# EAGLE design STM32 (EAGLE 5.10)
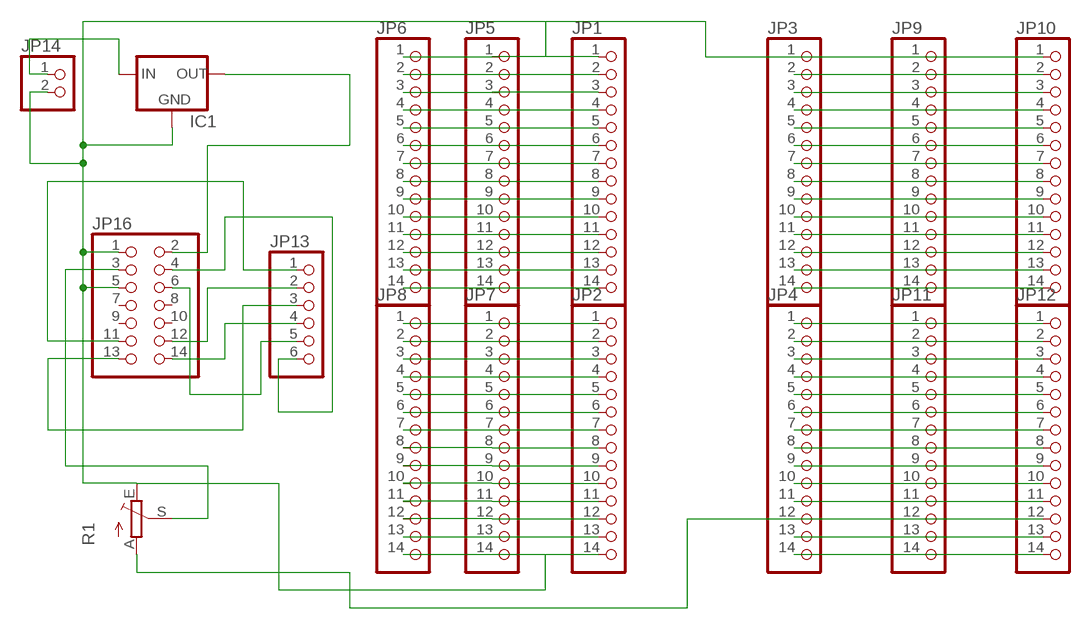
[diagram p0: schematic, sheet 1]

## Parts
IC1  78XXL  [78XXL]
JP1  PINHD-1X14  [1X14]
JP2  PINHD-1X14  [1X14]
JP3  PINHD-1X14  [1X14]
JP4  PINHD-1X14  [1X14]
JP5  PINHD-1X14  [1X14]
JP6  PINHD-1X14  [1X14]
JP7  PINHD-1X14  [1X14]
JP8  PINHD-1X14  [1X14]
JP9  PINHD-1X14  [1X14]
JP10  PINHD-1X14  [1X14]
JP11  PINHD-1X14  [1X14]
JP12  PINHD-1X14  [1X14]
JP13  PINHD-1X6  [1X06]
JP14  PINHD-1X2  [1X02]
JP16  PINHD-2X7  [2X07]
R1  TRIM_EU-LI15  [LI15]

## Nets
N$1: IC1.IN JP14.1
N$2: JP1.2 JP5.2 JP6.2
N$3: JP1.3 JP5.3 JP6.3
N$4: JP1.4 JP5.4 JP6.4
N$5: JP1.5 JP5.5 JP6.5
N$6: JP1.6 JP5.6 JP6.6
N$7: JP1.7 JP5.7 JP6.7
N$8: JP1.8 JP5.8 JP6.8
N$9: JP1.9 JP5.9 JP6.9
N$10: JP1.10 JP5.10 JP6.10
N$11: JP1.11 JP5.11 JP6.11
N$12: JP1.12 JP5.12 JP6.12
N$13: JP1.13 JP5.13 JP6.13
N$14: JP1.14 JP5.14 JP6.14
N$15: JP2.1 JP7.1 JP8.1
N$16: JP2.2 JP7.2 JP8.2
N$17: JP2.3 JP7.3 JP8.3
N$18: JP2.4 JP7.4 JP8.4
N$19: JP2.5 JP7.5 JP8.5
N$20: JP2.6 JP7.6 JP8.6
N$21: JP2.7 JP7.7 JP8.7
N$22: JP13.4 JP16.14
N$23: JP13.2 JP16.12
N$24: JP13.3 JP16.13
N$25: JP13.1 JP16.11
N$26: JP13.5 JP16.6
N$27: JP13.6 JP16.4
N$28: JP16.3 R1.S
N$29: JP2.8 JP7.8 JP8.8
N$30: JP2.9 JP7.9 JP8.9
N$31: JP2.10 JP7.10 JP8.10
N$32: JP2.11 JP7.11 JP8.11
N$33: JP2.12 JP7.12 JP8.12
N$34: JP2.13 JP7.13 JP8.13
N$35: IC1.OUT JP16.2
N$36: JP4.14 JP11.14 JP12.14
N$37: JP4.13 JP11.13 JP12.13
N$38: JP4.12 JP11.12 JP12.12 R1.A
N$39: JP4.11 JP11.11 JP12.11
N$40: JP4.10 JP11.10 JP12.10
N$41: JP4.9 JP11.9 JP12.9
N$42: JP4.8 JP11.8 JP12.8
N$43: JP4.7 JP11.7 JP12.7
N$44: JP4.6 JP11.6 JP12.6
N$45: JP4.5 JP11.5 JP12.5
N$46: JP4.4 JP11.4 JP12.4
N$47: JP4.3 JP11.3 JP12.3
N$48: JP4.2 JP11.2 JP12.2
N$49: JP4.1 JP11.1 JP12.1
N$50: JP3.14 JP9.14 JP10.14
N$51: JP3.13 JP9.13 JP10.13
N$52: JP3.12 JP9.12 JP10.12
N$53: JP3.11 JP9.11 JP10.11
N$54: JP3.10 JP9.10 JP10.10
N$55: JP3.9 JP9.9 JP10.9
N$56: JP3.8 JP9.8 JP10.8
N$57: JP3.7 JP9.7 JP10.7
N$58: JP3.6 JP9.6 JP10.6
N$59: JP3.5 JP9.5 JP10.5
N$60: JP3.4 JP9.4 JP10.4
N$61: JP3.3 JP9.3 JP10.3
N$62: JP3.2 JP9.2 JP10.2
N$63: IC1.GND JP1.1 JP2.14 JP3.1 JP5.1 JP6.1 JP7.14 JP8.14 JP9.1 JP10.1 JP14.2 JP16.1 JP16.5 R1.E
Unconnected: JP16.7 JP16.8 JP16.9 JP16.10

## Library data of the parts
IC1 = v-reg:78XXL: VOLTAGE REGULATOR
JP1-JP12 = pinhead:PINHD-1X14: PIN HEADER
JP13 = pinhead:PINHD-1X6: PIN HEADER
JP14 = pinhead:PINHD-1X2: PIN HEADER
JP16 = pinhead:PINHD-2X7: PIN HEADER
R1 = pot:TRIM_EU-: POTENTIOMETER

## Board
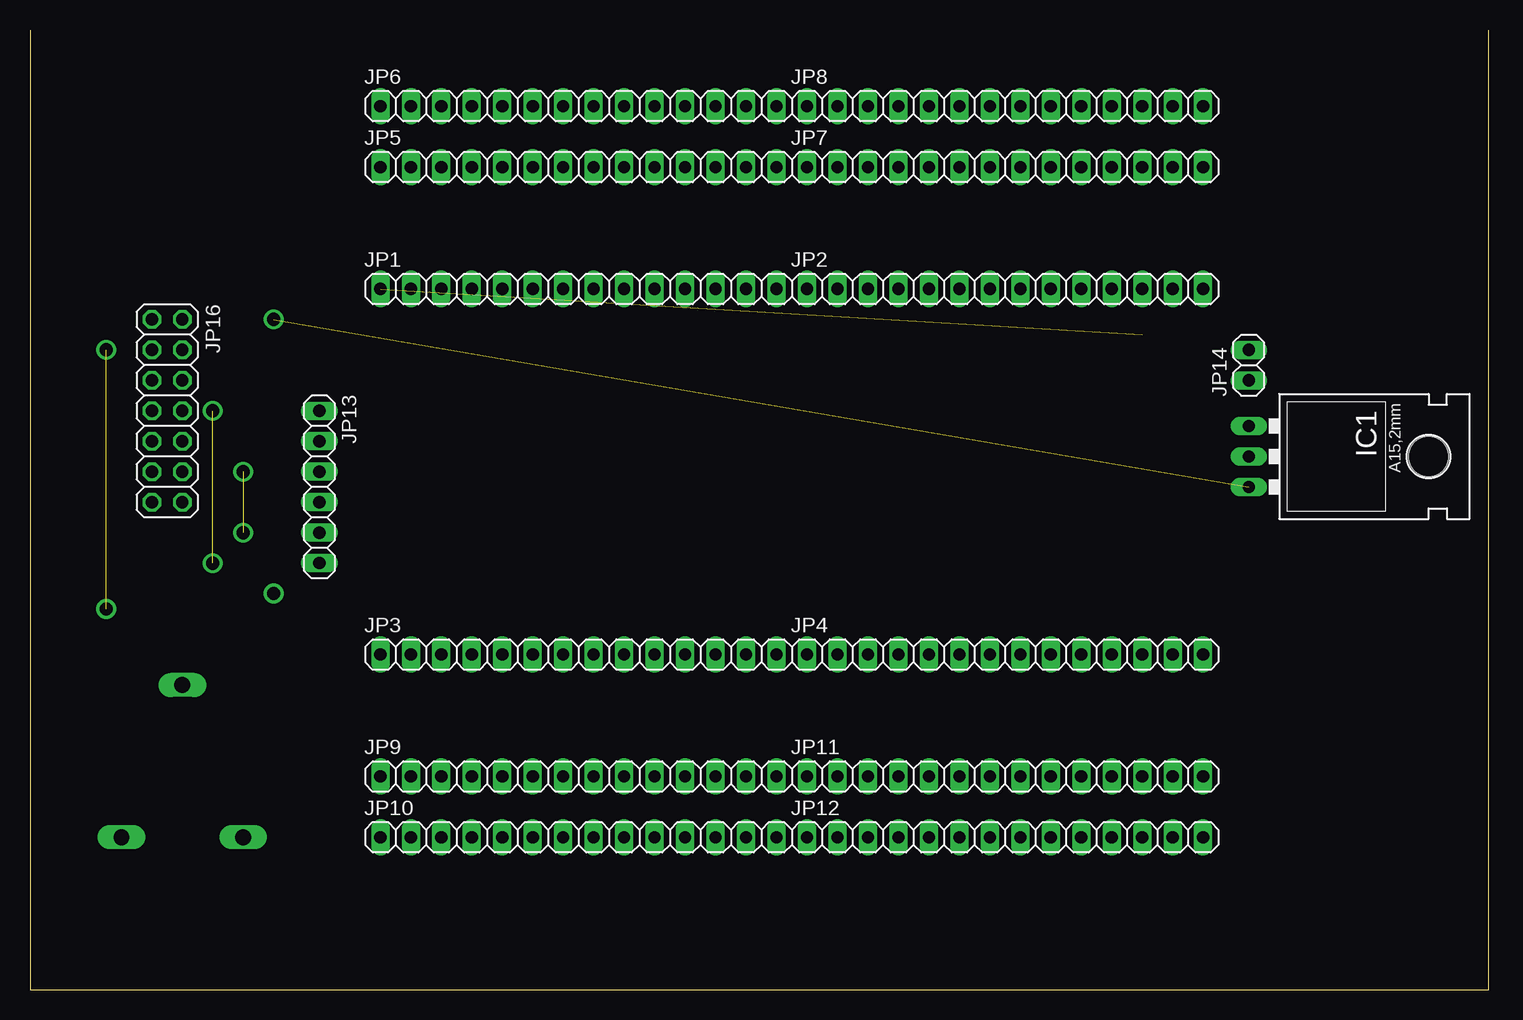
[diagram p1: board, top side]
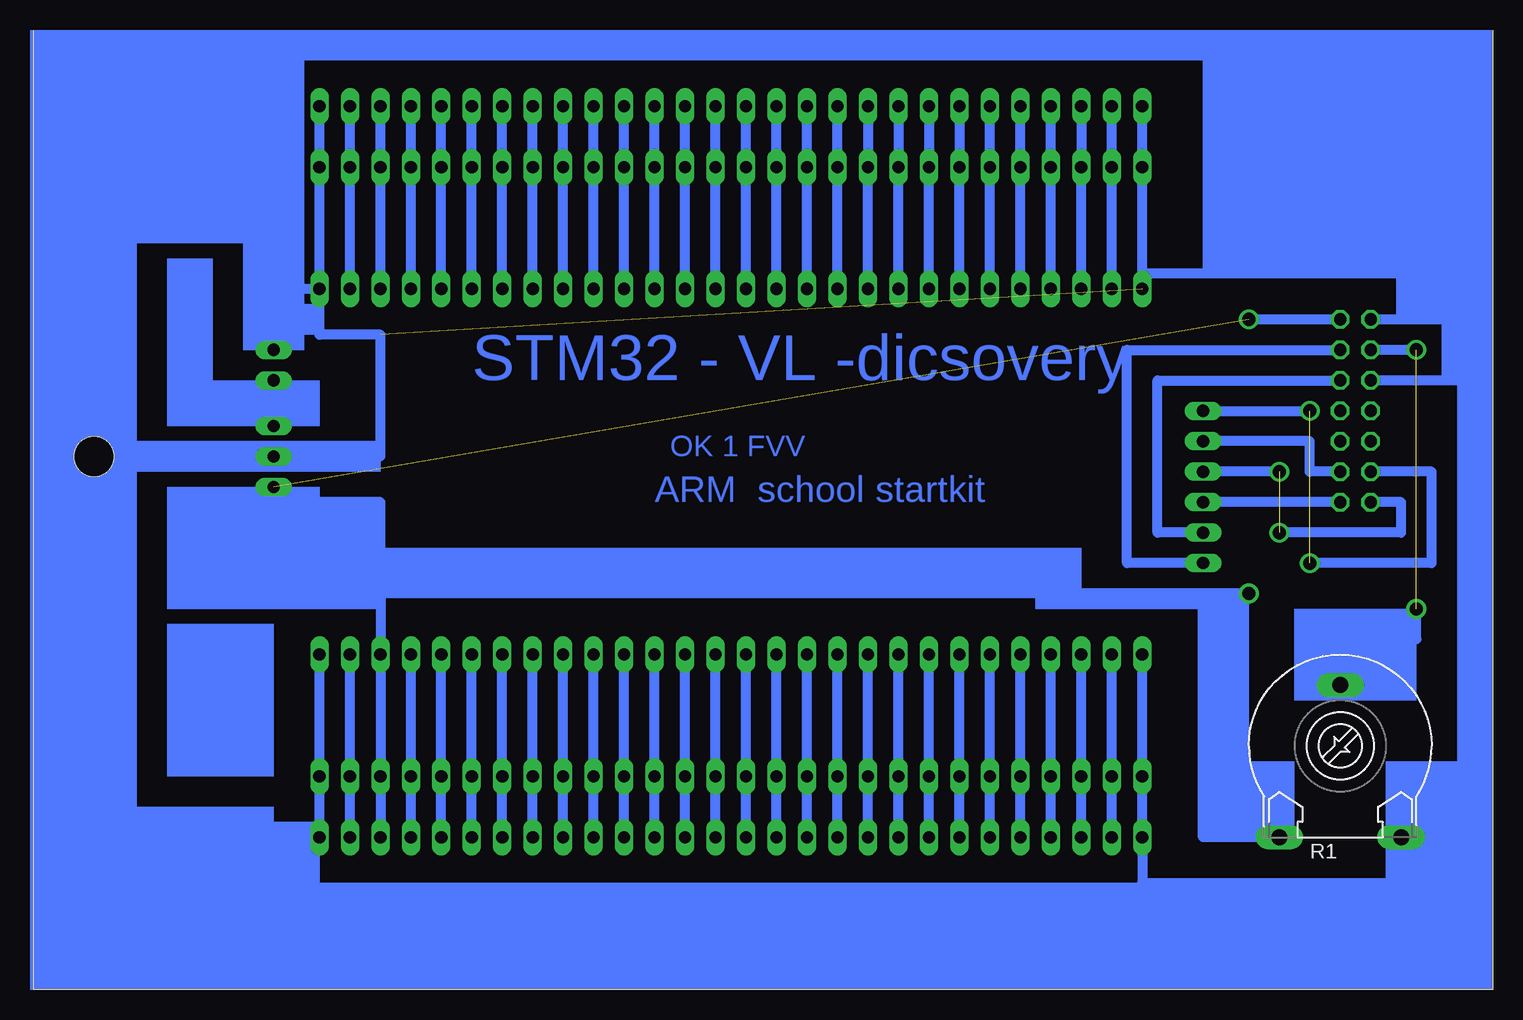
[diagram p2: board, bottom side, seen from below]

Size 121.59 x 80 mm. Coordinates in mm from the lower left corner, seen from the top.
Outline: 121.59,80 121.59,0 0,0 0,80
Copper layers (1*16): Top 0.035mm / dielectric 1.5mm / Bottom 0.035mm
Design rules: minimum track width 10mil, minimum drill 24mil, track to track 8mil, track to pad 8mil, pad to pad 8mil, via to via 8mil, smd to smd 8mil, copper to edge 40mil, drill to drill 8mil, minimum pad ring 10mil, minimum via ring 8mil, stop-mask expansion 4mil, vias tented up to drill 0mil, thermal gap 10mil

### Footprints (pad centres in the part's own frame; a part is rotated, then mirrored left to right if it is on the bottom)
78XXL = drill 1.016 long: GND 0,-3.81; IN -2.54,-3.81; OUT 2.54,-3.81 | hole 3.302: 0,11.176
1X14 = drill 1.016 long: 1 -16.51,0; 2 -13.97,0; 3 -11.43,0; 4 -8.89,0; 5 -6.35,0; 6 -3.81,0; 7 -1.27,0; 8 1.27,0; 9 3.81,0; 10 6.35,0; 11 8.89,0; 12 11.43,0; 13 13.97,0; 14 16.51,0
1X06 = drill 1.016 long: 1 -6.35,0; 2 -3.81,0; 3 -1.27,0; 4 1.27,0; 5 3.81,0; 6 6.35,0
1X02 = drill 1.016 long: 1 -1.27,0; 2 1.27,0
2X07 = drill 1.016 octagon: 1 -7.62,-1.27; 2 -7.62,1.27; 3 -5.08,-1.27; 4 -5.08,1.27; 5 -2.54,-1.27; 6 -2.54,1.27; 7 0,-1.27; 8 0,1.27; 9 2.54,-1.27; 10 2.54,1.27; 11 5.08,-1.27; 12 5.08,1.27; 13 7.62,-1.27; 14 7.62,1.27
LI15 = drill 1.321 long: A -5.08,-7.62; E 5.08,-7.62; S 0,5.08

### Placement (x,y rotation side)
IC1  105.41,44.45 270 top
JP1  45.72,58.42 0 top
JP2  81.28,58.42 0 top
JP3  45.72,27.94 0 top
JP4  81.28,27.94 0 top
JP5  45.72,68.58 0 top
JP6  45.72,73.66 0 top
JP7  81.28,68.58 0 top
JP8  81.28,73.66 0 top
JP9  45.72,17.78 0 top
JP10  45.72,12.7 0 top
JP11  81.28,17.78 0 top
JP12  81.28,12.7 0 top
JP13  24.13,41.91 270 top
JP14  101.6,52.07 90 top
JP16  11.43,48.26 270 top
R1  12.7,20.32 0 bottom

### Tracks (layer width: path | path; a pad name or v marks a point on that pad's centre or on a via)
N$1
  Bottom 0.813: JP14.1 IC1.IN
N$2
  Bottom 0.813: JP6.2 JP5.2 JP1.2
N$3
  Bottom 0.813: JP1.3 JP5.3 JP6.3
N$4
  Bottom 0.813: JP6.4 JP5.4 JP1.4
N$5
  Bottom 0.813: JP6.5 JP5.5 JP1.5
N$6
  Bottom 0.813: JP6.6 JP5.6 JP1.6
N$7
  Bottom 0.813: JP1.7 JP5.7 JP6.7
N$8
  Bottom 0.813: JP1.8 JP5.8 JP6.8
N$9
  Bottom 0.813: JP1.9 JP5.9 JP6.9
N$10
  Bottom 0.813: JP1.10 JP5.10 JP6.10
N$11
  Bottom 0.813: JP6.11 JP5.11 JP1.11
N$12
  Bottom 0.813: JP6.12 JP5.12 JP1.12
N$13
  Bottom 0.813: JP6.13 JP5.13 JP1.13
N$14
  Bottom 0.813: JP6.14 JP5.14 JP1.14
N$15
  Bottom 0.813: JP8.1 JP7.1 JP2.1
N$16
  Bottom 0.813: JP8.2 JP7.2 JP2.2
N$17
  Bottom 0.813: JP8.3 JP7.3 JP2.3
N$18
  Bottom 0.813: JP8.4 JP7.4 JP2.4
N$19
  Bottom 0.813: JP8.5 JP7.5 JP2.5
N$20
  Bottom 0.813: JP8.6 JP7.6 JP2.6
N$21
  Bottom 0.813: JP8.7 JP7.7 JP2.7
N$22
  Bottom 0.813: JP16.14 JP13.4
N$23
  Bottom 0.813: JP16.12 15.24,43.18 15.24,45.72 JP13.2
N$24  (via drill 1.1 pad 0.81)  (1 unrouted)
  Bottom 0.813: JP16.13 7.62,40.64 7.62,38.1 v17.78,38.1 | v17.78,43.18 JP13.3
N$25  (via drill 1.1 pad 0.81)  (1 unrouted)
  Bottom 0.813: JP16.11 5.08,43.18 5.08,35.56 v15.24,35.56 | JP13.1 v15.24,48.26
N$26
  Bottom 0.813: JP13.5 27.94,38.1 27.94,50.8 JP16.6
N$27
  Bottom 0.813: JP13.6 30.48,35.56 30.48,53.34 JP16.4
N$28  (via drill 1.1 pad 0.81)  (1 unrouted)
  Bottom 0.813: v6.35,53.34 JP16.3 | R1.S 12.7,29.21 6.35,29.21 v6.35,31.75
N$29
  Bottom 0.813: JP8.8 JP7.8 JP2.8
N$30
  Bottom 0.813: JP8.9 JP7.9 JP2.9
N$31
  Bottom 0.813: JP8.10 JP7.10 JP2.10
N$32
  Bottom 0.813: JP8.11 JP7.11 JP2.11
N$33
  Bottom 0.813: JP8.12 JP7.12 JP2.12
N$34
  Bottom 0.813: JP8.13 JP7.13 JP2.13
N$35  (via drill 1.1 pad 0.81)  (1 unrouted)
  Bottom 0.813: JP16.2 v20.32,55.88
N$36
  Bottom 0.813: JP4.14 JP11.14 JP12.14
N$37
  Bottom 0.813: JP4.13 JP11.13 JP12.13
N$38  (via drill 1.1 pad 0.81)
  Bottom 0.813: JP12.12 JP11.12 JP4.12 92.71,33.02 | 22.86,12.7 R1.A 24.13,12.7 24.13,33.02 v20.32,33.02 92.71,33.02 | 92.71,33.02 92.71,40.64 101.6,40.64
N$39
  Bottom 0.813: JP4.11 JP11.11 JP12.11
N$40
  Bottom 0.813: JP4.10 JP11.10 JP12.10
N$41
  Bottom 0.813: JP4.9 JP11.9 JP12.9
N$42
  Bottom 0.813: JP4.8 JP11.8 JP12.8
N$43
  Bottom 0.813: JP4.7 JP11.7 JP12.7
N$44
  Bottom 0.813: JP4.6 JP11.6 JP12.6
N$45
  Bottom 0.813: JP4.5 JP11.5 JP12.5
N$46
  Bottom 0.813: JP4.4 JP11.4 JP12.4
N$47
  Bottom 0.813: JP4.3 JP11.3 JP12.3
N$48
  Bottom 0.813: JP4.2 JP11.2 JP12.2
N$49
  Bottom 0.813: JP4.1 JP11.1 JP12.1
N$50
  Bottom 0.813: JP3.14 JP9.14 JP10.14
N$51
  Bottom 0.813: JP3.13 JP9.13 JP10.13
N$52
  Bottom 0.813: JP3.12 JP9.12 JP10.12
N$53
  Bottom 0.813: JP3.11 JP9.11 JP10.11
N$54
  Bottom 0.813: JP3.10 JP9.10 JP10.10
N$55
  Bottom 0.813: JP3.9 JP9.9 JP10.9
N$56
  Bottom 0.813: JP3.8 JP9.8 JP10.8
N$57
  Bottom 0.813: JP3.7 JP9.7 JP10.7
N$58
  Bottom 0.813: JP3.6 JP9.6 JP10.6
N$59
  Bottom 0.813: JP3.5 JP9.5 JP10.5
N$60
  Bottom 0.813: JP3.4 JP9.4 JP10.4
N$61
  Bottom 0.813: JP3.3 JP9.3 JP10.3
N$62
  Bottom 0.813: JP3.2 JP9.2 JP10.2
N$63  (1 unrouted)
  Bottom 0.813: JP6.1 JP5.1 JP1.1 29.21,59.69 7.62,59.69 7.62,55.88 | 7.62,55.88 JP16.1 | 3.81,50.8 JP16.5 | 3.81,50.8 3.81,55.88 7.62,55.88 | 3.81,50.8 2.54,50.8 2.54,12.7 R1.E | R1.E 7.62,11.43 | JP3.1 JP9.1 JP10.1 29.21,8.89 7.62,8.89 R1.E | IC1.GND 92.71,44.45 92.71,54.61 97.79,54.61 JP2.14 | JP8.14 JP7.14 JP2.14 | JP14.2 101.6,58.42 JP2.14
(copper drawn outside any net)
  shapes: Bottom area x32

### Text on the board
Bottom: STM32 - VL -dicsovery | OK 1 FVV | ARM school startkit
